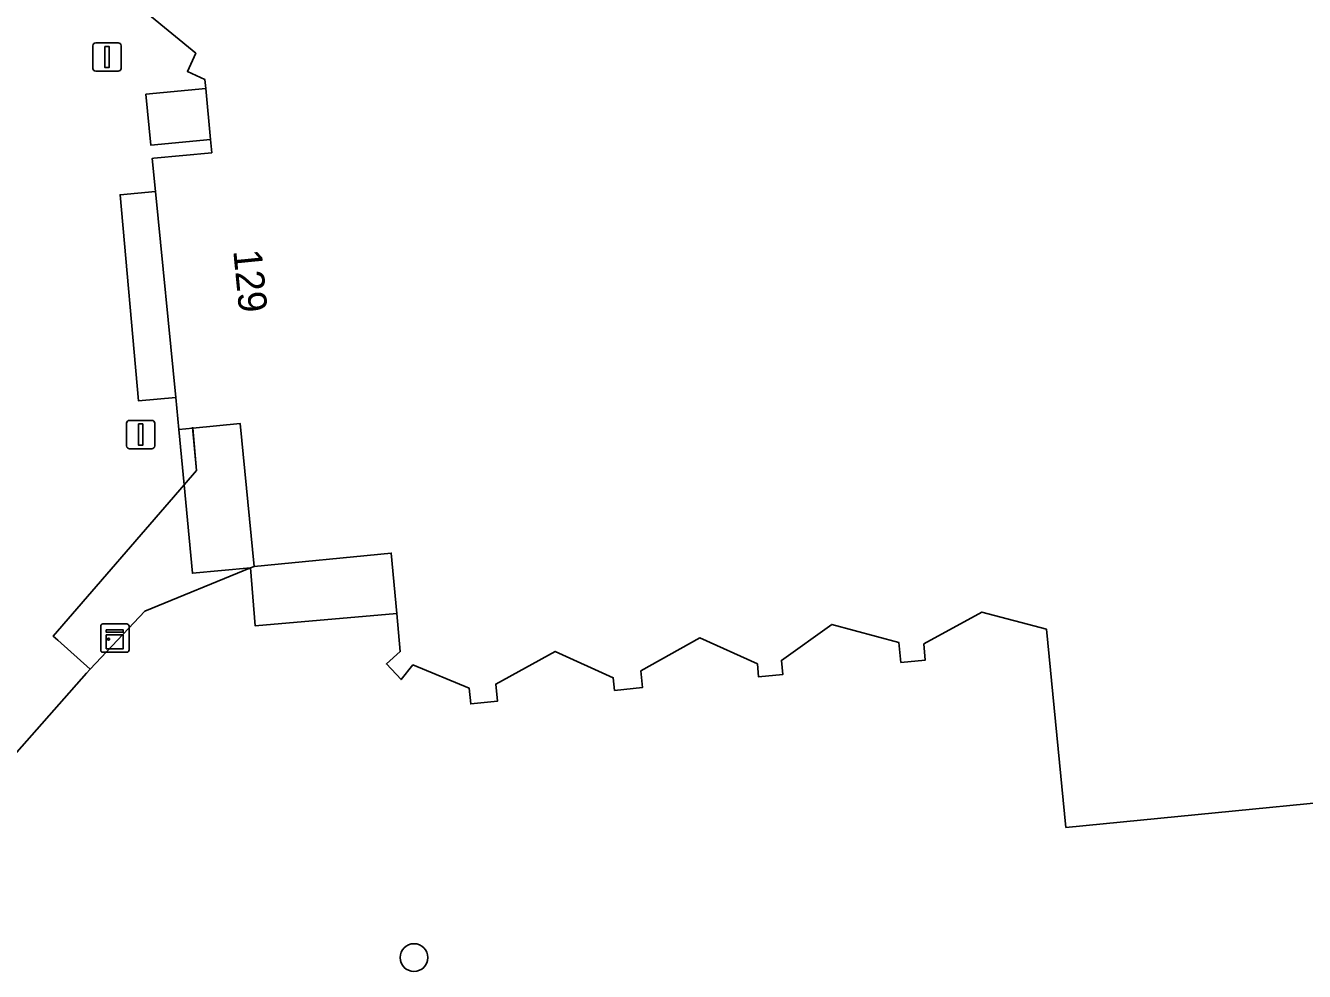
# Model space of a CAD drawing. Extents: x 159371 to 159986, y 382987 to 383597.
# Drawn here: x 159689.17 to 159734.23, y 383519.52 to 383552.86 of the extents above; entities that cross this region are included whole.
import ezdxf

# ---------------------------------------------------------------- set-up
doc = ezdxf.new("R2010")
doc.units = 0
for name, color, linetype in [('IMGEO_Boom', 7, 'Continuous'), ('IMGEO_Erf', 7, 'Continuous'), ('IMGEO_Kast', 7, 'Continuous'), ('IMGEO_Lichtmast', 7, 'Continuous'), ('IMGEO_Muur', 7, 'Continuous'), ('IMGEO_Pand', 7, 'Continuous'), ('IMGEO_Pand_nummerreeks', 7, 'Continuous'), ('IMGEO_Voetpad_open', 7, 'Continuous')]:
    doc.layers.add(name, color=color, linetype=linetype)

msp = doc.modelspace()

# ---------------------------------------------------------------- linework, layer by layer
at = {"layer": 'IMGEO_Boom'}
msp.add_circle((159702.855, 383520.008), 0.489, dxfattribs=at)
at = {"layer": 'IMGEO_Erf'}
msp.add_lwpolyline([(159740.892, 383526.075), (159725.826, 383524.597), (159725.142, 383531.576), (159722.867, 383532.183), (159720.819, 383531.064), (159720.874, 383530.495), (159720.013, 383530.41), (159719.945, 383531.108), (159717.579, 383531.752), (159715.801, 383530.479), (159715.85, 383529.979), (159715, 383529.896), (159714.955, 383530.355), (159712.925, 383531.276), (159710.849, 383530.113), (159710.907, 383529.521), (159709.922, 383529.425), (159709.879, 383529.87), (159707.83, 383530.799), (159705.737, 383529.645), (159705.796, 383529.042), (159704.858, 383528.95), (159704.804, 383529.498), (159702.817, 383530.319), (159702.398, 383529.806), (159701.886, 383530.356), (159702.369, 383530.794), (159702.247, 383532.133), (159697.256, 383531.7), (159697.093, 383533.741), (159693.367, 383532.213), (159691.441, 383530.17), (159691.309, 383530.03), (159685.704, 383523.677)], dxfattribs=at)
at = {"layer": 'IMGEO_Kast'}
for p, q in [((159691.814, 383530.841), (159691.814, 383531.682)), ((159691.814, 383531.682), (159691.814, 383530.841)), ((159691.889, 383531.766), (159692.73, 383531.766)), ((159692.73, 383531.766), (159691.889, 383531.766)), ((159692.814, 383531.691), (159692.814, 383530.85)), ((159692.814, 383530.85), (159692.814, 383531.691)), ((159692.739, 383530.766), (159691.898, 383530.766)), ((159691.898, 383530.766), (159692.739, 383530.766))]:
    msp.add_line(p, q, dxfattribs=at)
for points in [[(159692.009, 383531.556), (159692.609, 383531.556), (159692.609, 383531.471), (159692.009, 383531.471), (159692.009, 383531.556)], [(159692.009, 383531.381), (159692.609, 383531.381), (159692.609, 383530.892), (159692.009, 383530.892), (159692.009, 383531.381)]]:
    msp.add_lwpolyline(points, dxfattribs=at)
msp.add_circle((159692.093, 383531.23), 0.0377, dxfattribs=at)
for centre, start, end in [((159691.892, 383531.688), 92.4484, 184.2845), ((159691.892, 383531.688), 92.4484, 184.2845), ((159692.736, 383531.688), 2.4484, 94.2845), ((159692.736, 383531.688), 2.4484, 94.2845), ((159691.892, 383530.844), 182.4484, 274.2845), ((159691.892, 383530.844), 182.4484, 274.2845), ((159692.736, 383530.844), 272.4484, 4.2845), ((159692.736, 383530.844), 272.4484, 4.2845)]:
    msp.add_arc(centre, 0.0779, start, end, dxfattribs=at)
at = {"layer": 'IMGEO_Lichtmast'}
for p, q in [((159691.541, 383551.347), (159691.541, 383552.147)), ((159691.541, 383552.147), (159691.541, 383551.347)), ((159691.641, 383552.247), (159692.431, 383552.247)), ((159692.431, 383552.247), (159691.641, 383552.247)), ((159692.531, 383552.147), (159692.531, 383551.347)), ((159692.531, 383551.347), (159692.531, 383552.147)), ((159692.431, 383551.247), (159691.641, 383551.247)), ((159691.641, 383551.247), (159692.431, 383551.247)), ((159692.728, 383538.041), (159692.728, 383538.841)), ((159692.728, 383538.841), (159692.728, 383538.041)), ((159692.828, 383538.941), (159693.618, 383538.941)), ((159693.618, 383538.941), (159692.828, 383538.941)), ((159693.718, 383538.841), (159693.718, 383538.041)), ((159693.718, 383538.041), (159693.718, 383538.841)), ((159693.618, 383537.941), (159692.828, 383537.941)), ((159692.828, 383537.941), (159693.618, 383537.941))]:
    msp.add_line(p, q, dxfattribs=at)
for points in [[(159691.961, 383552.122), (159692.111, 383552.122), (159692.111, 383551.372), (159691.961, 383551.372), (159691.961, 383552.122)], [(159693.148, 383538.816), (159693.298, 383538.816), (159693.298, 383538.066), (159693.148, 383538.066), (159693.148, 383538.816)]]:
    msp.add_lwpolyline(points, dxfattribs=at)
for centre, start, end in [((159691.641, 383552.147), 90, 180), ((159691.641, 383552.147), 90, 180), ((159692.431, 383552.147), 0, 90), ((159692.431, 383552.147), 360, 90), ((159691.641, 383551.347), 180, 270), ((159691.641, 383551.347), 180, 270), ((159692.431, 383551.347), 270, 0), ((159692.431, 383551.347), 270, 0), ((159692.828, 383538.841), 90, 180), ((159692.828, 383538.841), 90, 180), ((159693.618, 383538.841), 0, 90), ((159693.618, 383538.841), 360, 90), ((159692.828, 383538.041), 180, 270), ((159692.828, 383538.041), 180, 270), ((159693.618, 383538.041), 270, 0), ((159693.618, 383538.041), 270, 0)]:
    msp.add_arc(centre, 0.1, start, end, dxfattribs=at)
at = {"layer": 'IMGEO_Muur'}
for points in [[(159695.054, 383538.698), (159695.189, 383537.176), (159694.752, 383536.671)], [(159694.752, 383536.671), (159690.134, 383531.338), (159690.309, 383531.193)], [(159691.441, 383530.17), (159693.367, 383532.213), (159697.093, 383533.741)], [(159685.704, 383523.677), (159691.309, 383530.03), (159691.441, 383530.17)]]:
    msp.add_lwpolyline(points, dxfattribs=at)
at = {"layer": 'IMGEO_Pand'}
msp.add_lwpolyline([(159693.478, 383553.275), (159695.164, 383551.882), (159694.869, 383551.237), (159695.484, 383550.955), (159695.514, 383550.639), (159695.685, 383548.844), (159695.73, 383548.372), (159693.692, 383548.178), (159693.633, 383548.172), (159693.747, 383547.011), (159694.459, 383539.747), (159694.57, 383538.616), (159695.057, 383538.664), (159696.733, 383538.828), (159697.227, 383533.789), (159702.054, 383534.262), (159702.247, 383532.133), (159702.369, 383530.794), (159701.886, 383530.356), (159702.398, 383529.806), (159702.817, 383530.319), (159704.804, 383529.498), (159704.858, 383528.95), (159705.796, 383529.042), (159705.737, 383529.645), (159707.83, 383530.799), (159709.879, 383529.87), (159709.922, 383529.425), (159710.907, 383529.521), (159710.849, 383530.113), (159712.925, 383531.276), (159714.955, 383530.355), (159715, 383529.896), (159715.85, 383529.979), (159715.801, 383530.479), (159717.579, 383531.752), (159719.945, 383531.108), (159720.013, 383530.41), (159720.874, 383530.495), (159720.819, 383531.064), (159722.867, 383532.183), (159725.142, 383531.576), (159725.826, 383524.597), (159740.892, 383526.075)], dxfattribs=at)
at = {"layer": 'IMGEO_Voetpad_open'}
msp.add_lwpolyline([(159685.704, 383523.677), (159691.309, 383530.03), (159691.441, 383530.17), (159690.309, 383531.193), (159690.134, 383531.338), (159694.752, 383536.671), (159694.57, 383538.616), (159694.459, 383539.747), (159693.147, 383539.628), (159692.498, 383546.891), (159693.747, 383547.011), (159693.633, 383548.172), (159693.692, 383548.178), (159695.73, 383548.372), (159695.685, 383548.844), (159693.587, 383548.639), (159693.411, 383550.432), (159695.514, 383550.639), (159695.484, 383550.955), (159694.869, 383551.237), (159695.164, 383551.882), (159693.478, 383553.275)], dxfattribs=at)
for points in [[(159693.411, 383550.432), (159693.587, 383548.639), (159695.685, 383548.844), (159695.514, 383550.639)], [(159692.498, 383546.891), (159693.147, 383539.628), (159694.459, 383539.747), (159693.747, 383547.011)], [(159695.189, 383537.176), (159694.752, 383536.671), (159695.045, 383533.552), (159697.093, 383533.741), (159697.227, 383533.789), (159696.733, 383538.828), (159695.057, 383538.664)], [(159694.57, 383538.616), (159694.752, 383536.671), (159695.189, 383537.176), (159695.057, 383538.664)], [(159690.309, 383531.193), (159691.441, 383530.17), (159693.367, 383532.213), (159697.093, 383533.741), (159695.045, 383533.552), (159694.752, 383536.671), (159690.134, 383531.338)], [(159697.227, 383533.789), (159697.093, 383533.741), (159697.256, 383531.7), (159702.247, 383532.133), (159702.054, 383534.262)]]:
    msp.add_lwpolyline(points, close=True, dxfattribs=at)

# ---------------------------------------------------------------- texts
at = {"layer": 'IMGEO_Pand_nummerreeks'}
msp.add_text('129', height=1, rotation=275.6002, dxfattribs=at).set_placement((159696.484, 383544.921))

doc.saveas('drawing.dxf')
